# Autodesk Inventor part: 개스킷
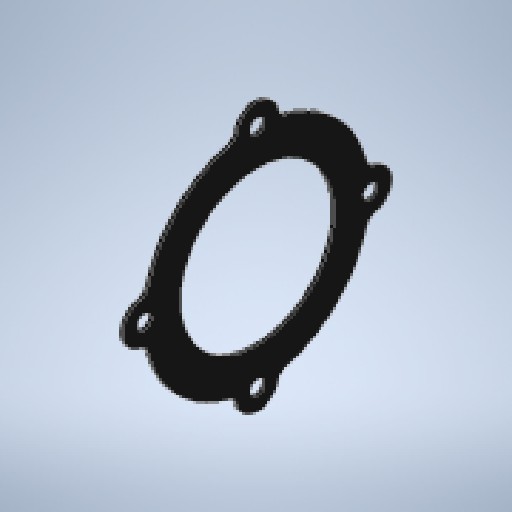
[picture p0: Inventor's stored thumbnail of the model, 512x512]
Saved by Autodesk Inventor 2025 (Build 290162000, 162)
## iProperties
Created: 2024-08
Part Number: 개스킷
Material: 황동, 연질 노란색
Document SubType Name: Modeling
Designer: Administrator
Density: 8.47 g/cm^3
Appearance: 기본값
Author: jhkim
Sending System: Autodesk Inventor 2025
Preprocessor: ST-DEVELOPER v20
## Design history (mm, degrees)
feature "솔리드2"
node "솔리드1"
